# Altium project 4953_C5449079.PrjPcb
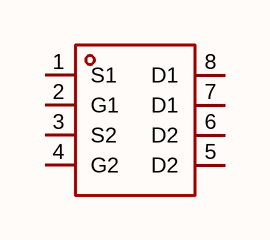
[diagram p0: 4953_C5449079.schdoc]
1 sheet, 1 parts. Net scope: global (net labels, ports and power ports of the same name join across sheets).

## Sheet 4953_C5449079.schdoc
size 127 x 101 mm

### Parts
Q?  4953_c5449079  [SOP-8_L4.9-W3.9-P1.27-LS6.0-BL]  (value not drawn)

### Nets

Not connected (* = marked no-connect by the designer): Q? 1(S1) 2(G1) 3(S2) 4(G2) 5(D2) 6(D2) 7(D1) 8(D1)

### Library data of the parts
Q? = 4953_c5449079: 数量:2个P沟道;漏源电压(Vdss):30V;连续漏极电流(Id):5.5A;导通电阻(RDS(on)):40mΩ@10V；60mΩ@4.5V;耗散功率(Pd):2.1W;阈值电压(Vgs(th)):1.6V;; Manufacturer: MSKSEMI(美森科); ManufacturerPart: 4953; AddInBom: yes; ModelId: 75c24a7891ee4dd6bdac16a7163ff87e; ModelName: SOP-8_L4.9-W3.9-P1.27-LS6.0-BL-1; ModelTransform: 192.913,236.22,0,0,0,0,-0.393,2.749,0; Number: 2个P沟道; Drain to Source Voltage: 30V; Current - Continuous Drain(Id): 5.5A; Pd - Power Dissipation: 2.1W; Gate Threshold Voltage (Vgs(th)): 1.6V; Gate Charge(Qg): 5.1nC@4.5V; Input Capacitance(Ciss): 560pF; Reverse Transfer Capacitance (Crss@Vds): 40pF; Type: P沟道; Output Capacitance(Coss): 55pF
